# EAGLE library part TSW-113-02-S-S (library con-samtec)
THROUGH-HOLE .025" SQ POST HEADER Source: Samtec TSW.pdf
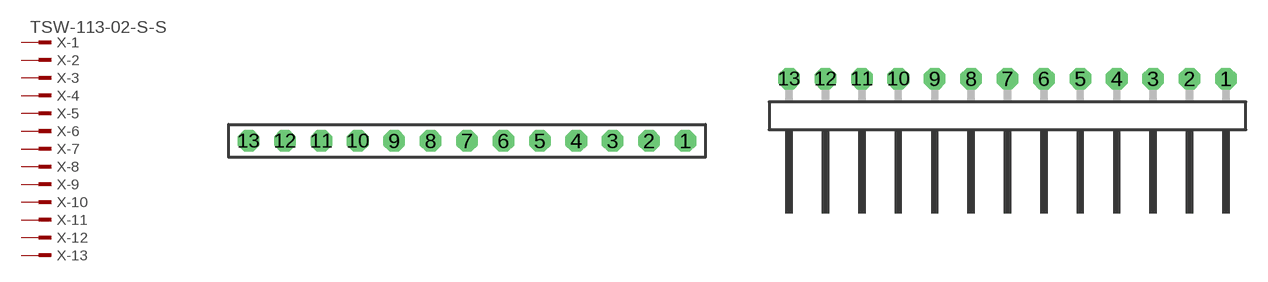
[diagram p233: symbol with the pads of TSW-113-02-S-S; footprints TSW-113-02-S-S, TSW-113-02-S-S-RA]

Designator prefix X; gates -1=MPINV -2=MPIN -3=MPIN -4=MPIN -5=MPIN -6=MPIN -7=MPIN -8=MPIN -9=MPIN -10=MPIN -11=MPIN -12=MPIN -13=MPIN

## TSW-113-02-S-S (OC_FARNELL: unknown; OC_NEWARK: unknown)  [TSW-113-02-S-S]
1  -1:1  pas
2  -2:1  pas
3  -3:1  pas
4  -4:1  pas
5  -5:1  pas
6  -6:1  pas
7  -7:1  pas
8  -8:1  pas
9  -9:1  pas
10  -10:1  pas
11  -11:1  pas
12  -12:1  pas
13  -13:1  pas

## TSW-113-02-S-S-RA (OC_FARNELL: unknown; OC_NEWARK: unknown)  [TSW-113-02-S-S-RA]
Pads as for TSW-113-02-S-S

## Footprint TSW-113-02-S-S (pad centres in mm)
THROUGH-HOLE .025" SQ POST HEADER Source: Samtec TSW.pdf
drill 1 pad 1.5 octagon: 1 15.24,0; 2 12.7,0; 3 10.16,0; 4 7.62,0; 5 5.08,0; 6 2.54,0; 7 0,0; 8 -2.54,0; 9 -5.08,0; 10 -7.62,0; 11 -10.16,0; 12 -12.7,0; 13 -15.24,0

## Footprint TSW-113-02-S-S-RA (pad centres in mm)
THROUGH-HOLE .025" SQ POST HEADER Source: Samtec TSW.pdf
drill 1 pad 1.5 octagon: 1 15.24,1.524; 2 12.7,1.524; 3 10.16,1.524; 4 7.62,1.524; 5 5.08,1.524; 6 2.54,1.524; 7 0,1.524; 8 -2.54,1.524; 9 -5.08,1.524; 10 -7.62,1.524; 11 -10.16,1.524; 12 -12.7,1.524; 13 -15.24,1.524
